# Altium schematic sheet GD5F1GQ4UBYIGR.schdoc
size 127 x 101 mm
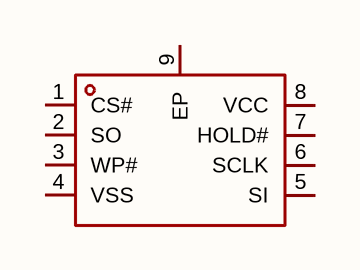
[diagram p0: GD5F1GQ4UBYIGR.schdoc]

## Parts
U?  gd5f1gq4ubyigr  [WSON-8_L8.0-W6.0-P1.27-TL-EP-1]  (value not drawn)

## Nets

Not connected (* = marked no-connect by the designer): U? 1(CS#) 2(SO) 3(WP#) 4(VSS) 5(SI) 6(SCLK) 7(HOLD#) 8(VCC) 9(EP)

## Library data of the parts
U? = gd5f1gq4ubyigr: 存储容量:1Gbit;时钟频率(fc):120MHz;工作电压:2.7V~3.6V;; Manufacturer: GigaDevice(兆易创新); AddInBom: yes; ModelId: 9b0b95cb42c44ddaa75bcc393c15d437; ModelTransform: 314.96,236.22,0,0,0,0,0,0,0; Memory Size: 1Gbit; Interface: SPI; Clock Frequency: 120MHz; Page Program time (TPP): 400us; Block Erase Time(tBE): 3ms; Standby Supply Current: 90uA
